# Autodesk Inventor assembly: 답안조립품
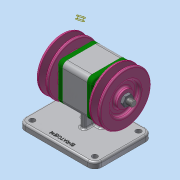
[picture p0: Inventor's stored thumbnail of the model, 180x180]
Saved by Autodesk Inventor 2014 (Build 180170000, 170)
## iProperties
Created: 2020-11
Part Number: 답안조립품
Document SubType Name: Assembly
Designer: kh
Author: kh
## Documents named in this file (10)
- C:\Users\kh\Desktop\701106V1020\답안조립품.iam
- C:\Users\kh\Desktop\701106V1020\본체.ipt
- C:\Users\kh\Desktop\701106V1020\베어링 6004.ipt
- C:\Users\kh\Desktop\701106V1020\축.ipt
- C:\Users\kh\Desktop\701106V1020\커버.ipt
- C:\Users\kh\Desktop\701106V1020\오일 실 17 30 5.ipt
- C:\Users\kh\Desktop\701106V1020\키 5 x 5 x 12.ipt
- C:\Users\kh\Desktop\701106V1020\V-벨트풀리.ipt
- C:\Users\kh\Desktop\701106V1020\볼트 M4.ipt
- C:\Users\kh\Desktop\701106V1020\너트 M10x1.ipt
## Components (2 placed, 1 different names)
1. V-벨트풀리:1
2. V-벨트풀리:2
## Component patterns: 구성요소 패턴 1:2 (2 elements)
